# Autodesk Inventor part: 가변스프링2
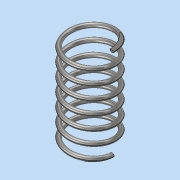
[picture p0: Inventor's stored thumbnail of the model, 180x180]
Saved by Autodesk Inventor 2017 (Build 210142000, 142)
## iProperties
Part Number: 가변스프링2
Material: 스테인레스 스틸
Document SubType Name: Modeling
Designer: MRC
Density: 8 g/cm^3
Appearance: 반연마
Mass: 10.9602 g
Surface Area: 27.6886 cm^2
Volume: 1.37003 cm^3
Author: MRC
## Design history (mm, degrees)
sketch "스케치1"
  geometry: L1 (0, 0)-(10, 0); L2 (10, 0)-(10, 41.177); L3 (10, 41.177)-(0, 41.177); L4 (0, 41.177)-(0, 0); C1 r 1 at (10, 0)
  constraints: 8 end point, 2 parallel, 1 centre point, 1 coincident, 1 horizontal, 1 perpendicular
  dimensions: "d0" = 20 diameter of L2 L4; "d1" = 41.17674 distance of L1.end L2.end (derived); "d2" = 2 diameter of C1
feature "코일1" sketch "스케치1" pitch "d3" = 10; turns "d5" = 7; dims "d4" = 41.17674 (= d1), "d6" = 0, angle "d7" = 90 deg, angle "d8" = 90 deg, "d9" = 0, "d10" = 0
sketch "스케치2"
  geometry: L1 (-15, 41.177)-(15, 41.177); L2 (15, 41.177)-(15, 0); L3 (15, 0)-(-15, 0); L4 (-15, 0)-(-15, 41.177); L5 (0, 41.177)-(0, 0) reference; 2 further points
  constraints: 8 end point, 2 midpoint, 2 parallel, 1 coincident, 1 horizontal, 1 perpendicular
  dimensions: "d11" = 30 distance of L1.start L1.end
extrude "돌출1" sketch "스케치2" stored distance "d12" = 0; taper "d13" = 0 deg
node "솔리드1"
